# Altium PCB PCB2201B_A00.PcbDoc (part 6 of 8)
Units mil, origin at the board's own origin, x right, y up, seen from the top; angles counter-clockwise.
Board outline 4523.63 x 2358.23 mil, 6 copper layers (Top Layer, Signal Layer 2, Signal Layer 3, Signal Layer 4, Signal Layer 5, Bottom Layer), stack 61.221 mil thick; 383 components, 308 nets, 1386 pads, 1147 vias.
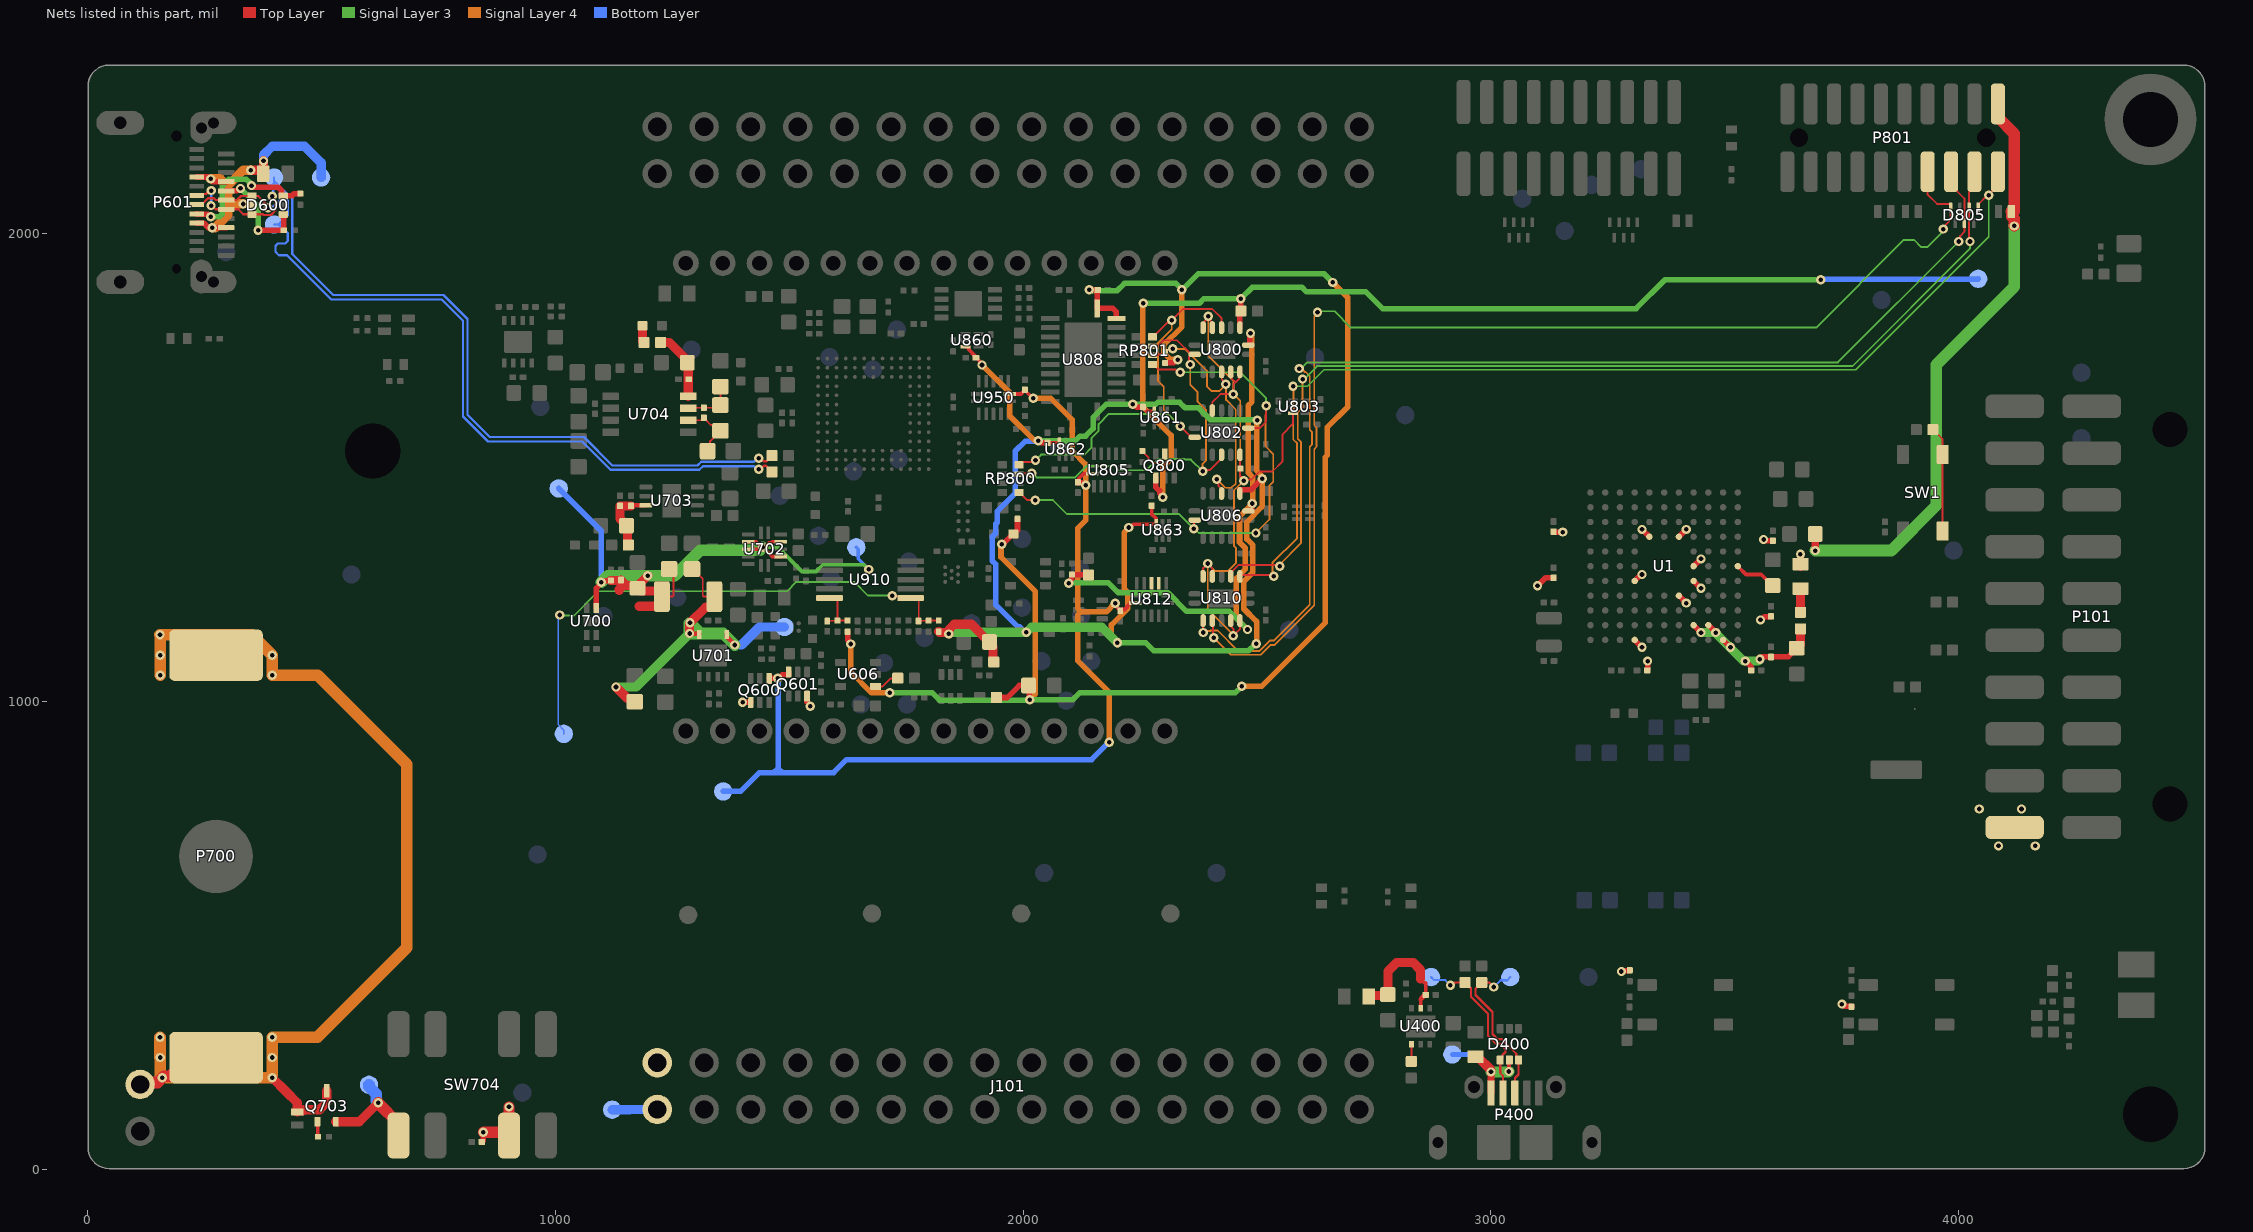
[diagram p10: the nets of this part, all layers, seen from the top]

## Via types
v1: diameter 19.68, hole 9.84, Top Layer to Bottom Layer, tented both sides, 768 vias
v2: diameter 20, hole 9.84, Top Layer to Bottom Layer, tented both sides, 379 vias

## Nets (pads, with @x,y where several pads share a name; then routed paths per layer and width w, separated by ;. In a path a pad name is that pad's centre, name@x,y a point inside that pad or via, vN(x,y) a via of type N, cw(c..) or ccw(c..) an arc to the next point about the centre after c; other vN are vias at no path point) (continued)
N17262717: C770.1 R769.1 R771.2 U704.6 | length 137.3
  Top Layer w3.94: U704.6@1284.67,1601.38 1312.99,1601.38 C770.1@1317.91,1606.3 1317.91,1605.51 1322.24,1601.18 1323.03,1601.18 1333.17,1591.04 1341.05,1591.04 R769.1@1353.35,1578.74 1331.35,1556.75 1331.35,1541 R771.2@1325.79,1535.43
N17262723: C770.2 R768.1 R769.2 U704.7 | length 110.9
  Top Layer w3.94: U704.7@1284.67,1626.97 1285.65,1627.95 C770.2@1317.91,1627.95 1347.44,1627.95 R769.2@1353.35,1633.86 R768.1@1353.35,1673.23
N17263058: C730.1 C731.1 R731.1 U704.8 | length 153.7
  Top Layer w19.68: R731.1@1225.39,1767.72 1244.09,1767.72 1282.48,1729.33 C731.1@1282.48,1724.41 1284.65,1722.24 1284.65,1654.74 1282.48,1654.74 U704.8@1284.67,1652.56
N17263074: L704.2 R731.2 | length 36.7
  Top Layer w19.68: L704.2@1187.01,1803.15 1187.01,1770.67 R731.2@1189.96,1767.72
N17356200: Q800.2 R815.1 | length 73.6
  Top Layer w3.94: R815.1@2254.95,1535.69 2254.95,1535.29 2267.93,1522.32 2267.93,1518.49 2276.57,1509.84 2290.35,1509.84 2303.15,1522.64 Q800.2@2303.15,1529.53
N17454530: D703.1 P700.1 Q703.3 ST701.2 | length 2370.9
  Top Layer w20: v2(395.51,196.11) 424.93,166.69 448.94,142.71 D703.1@448.94,122.95 451.06,125.08 460.66,125.08 463.48,127.9 496.76,127.9 511.81,142.95 Q703.3@511.81,168.31
  Top Layer w25: ST701.2@113.19,181.89 117.32,186.02 150.8,186.02 v2(160.89,196.11) 164.03,199.26 177.99,199.26 218.02,239.29 314.96,239.29 P700.1@327.87,226.38 ; P700.1@308.89,1099.29 P700.1@317.59,1107.99
  Signal Layer 4 w25: v2(155.81,282.73) 155.81,239.58 v2(155.97,239.42) 155.97,201.04 v2(160.89,196.11) v2(395.51,196.11) v2(395.51,239.42) v2(395.51,282.73) 492.14,282.73 683.15,473.74 683.15,865.98 493.02,1056.11 v2(395.51,1056.11) v2(395.51,1099.42) 352.2,1142.73 v2(155.81,1142.73) 155.97,1142.57 v2(155.97,1099.42) v2(155.97,1056.11)
N17454556: Q703.2 SW704.1 TP156.1 | length 236.1
  Top Layer w20: Q703.2@531.5,102.36 581.69,102.36 v1(622.05,142.72)
  Top Layer w25: v1(622.05,142.72) 622.05,141.73 665.35,98.43 665.35,91.54 SW704.1@665.35,72.83
  Bottom Layer w25: TP156.1@602.36,181.1 602.36,177.21 618.11,161.47 v1@618.11,146.65
N17454707: Q703.1 R792.2 | length 32.8
  Top Layer w8: Q703.1@492.13,102.36 492.8,101.69 492.8,70.83 R792.2@493.46,70.16
N17455720: L1.2 R2.1 | length 47.7
  Top Layer w19.68: L1.2@3660.43,1238.19 3661.42,1237.2 R2.1@3661.42,1190.94
N17455730: C3.1 C4.1 C5.1 R2.2 U1.K8 U1.K9 U1.L10 | length 381
  Top Layer w11.81: U1.K8@3433.07,1163.39 v1(3448.85,1147.59) ; U1.K9@3464.57,1163.39 v1(3480.35,1147.59) ; U1.L10@3496.06,1131.89 v1(3511.85,1116.09) ; v1(3543.3,1086.61) 3544.07,1086.61 3554.92,1075.76 3554.92,1067.32 3555.31,1066.93 C4.1@3556.1,1066.93 ; v1(3574.8,1090.55) 3579.72,1095.47 C5.1@3598.43,1095.47 3601.38,1095.47 3634.84,1095.47 ; 3635.83,1096.46 3634.84,1095.47 ; C3.1@3653.54,1114.17 3634.84,1095.47
  Top Layer w19.68: C3.1@3653.54,1114.17 3661.41,1122.04 R2.2@3661.42,1155.51
  Signal Layer 3 w19.68: v1(3448.85,1147.59) v1(3480.35,1147.59) 3480.35,1146.29 3540.03,1086.61 v1(3543.3,1086.61) 3570.86,1086.61 v1(3574.8,1090.55)
N17455955: C16.1 U1.F11 | length 92.7
  Top Layer w8: U1.F11@3527.56,1289.37 3545.28,1271.65 3577.76,1271.65 3601.2,1248.21 C16.1@3603.17,1248.21
N17456044: R7.2 SW1.3 SW1.4 | length 225.1
  Top Layer w3.94: R7.2@3944.36,1581.16 3965.23,1560.29 SW1.4@3965.23,1528.1 SW1.3@3965.23,1364.71
N17457251: D400.6 P400.3 R405.1 TPJ403.1 | length 361.8
  Top Layer w4.72: v1(3005.94,390.19) 2996.52,399.61 R405.1@2980.31,399.61 2966.95,386.24 2966.95,373.02 3003.19,336.78 3003.19,289.88 3014.58,278.5 3023.16,278.5 3054.04,247.62 3054.04,239.27 D400.6@3059.05,234.25 3059.05,203.15 3051.5,195.59 3051.5,163.96 P400.3@3051.2,163.66
  Bottom Layer w4.72: v1@3005.91,389.76 3020.8,404.66 3034.61,404.66 TPJ403.1@3041.35,411.39
N17457255: D400.4 P400.2 R406.1 TPJ404.1 | length 366.5
  Top Layer w4.72: v1(2913.39,393.7) 2917.43,393.7 2923.34,399.61 R406.1@2944.88,399.61 2957.5,386.99 2957.5,369.11 2993.74,332.87 2993.74,285.97 3010.66,269.05 3019.24,269.05 3031.1,257.19 3031.1,251.27 3024.7,244.87 3024.7,239.27 D400.4@3019.68,234.25 3019.68,206.14 3025.61,200.21 P400.2@3025.61,163.66
  Bottom Layer w4.72: TPJ404.1@2872.05,411.39 2878.55,404.9 2902.19,404.9 v1(2913.39,393.7)
N17457259: D400.5 L401.1 P400.1 TPJ405.1 | length 346.5
  Top Layer w7.87: v1(3038.39,209.65) 3038.39,233.27 D400.5@3039.37,234.25
  Top Layer w11.81: L401.1@2967.17,241.34 2968.9,241.34 2976.18,234.06 2976.18,232.48 v1(3000,208.66) 3000,189.36 2999.8,189.17 P400.1@2999.8,163.39
  Top Layer w15.75: P400.1@3000.02,163.66 v1(3000,208.66)
  Top Layer w19.68: L401.1@2968.9,241.34 2971.3,241.34 3000,212.64 v1(3000,208.66)
  Signal Layer 3 w23.62: v1(3000,208.66) 3037.4,208.66 v1(3038.39,209.65)
  Bottom Layer w9.84: TPJ405.1@2917.35,245.99 2962.67,245.99 v1(3000,208.66)
N17457715: C419.1 C423.1 L402.2 U400.2 | length 282.6
  Top Layer w7.87: 2849.53,407.48 2857.68,399.33 2860.16,399.33 2860.58,398.9 C419.1@2860.58,373.41 ; U400.2@2849.88,344.53 2849.88,363.49 2849.88,366.43 2854.49,371.05 C419.1@2857.43,371.05
  Top Layer w10: 2849.88,363.49 2857.43,371.05 2859.8,373.41 C419.1@2860.58,373.41
  Top Layer w19.68: L402.2@2738.78,370.08 2740.79,372.09 C423.1@2781.54,372.09 ; C423.1@2779.72,374.09 2779.72,423.43 2798.71,442.41 2833.78,442.41 2849.53,426.66 2849.53,407.48
N17457806: R408.2 U400.4 | length 36.9
  Top Layer w4: R408.2@2829.68,231.02 2829.68,239.12 2830.2,239.63 U400.4@2830.2,267.76
N17631739: R679.1 U606.1 | length 54.2
  Top Layer w3.94: U606.1@1685.04,1032.48 1699.8,1032.48 1716.54,1049.21 R679.1@1732.28,1049.21
SI_HEADER_ENABLE: R807.1 U800.5 U800.6 U800.12 U800.13 U802.5 U802.13 U803.3 U810.5 U810.6 U810.12 U810.13 | length 1429.8
  Top Layer w3.94: U810.6@2384.84,1267.72 2384.84,1285.43 v2(2394.68,1295.28) 2404.53,1285.43 U810.5@2404.53,1267.72 ; U800.6@2384.84,1799.21 2384.84,1809.22 2395.67,1820.04 v2(2395.67,1823.82) 2398.74,1820.75 2398.74,1815 2404.53,1809.22 U800.5@2404.53,1799.21 ; U802.5@2404.53,1622.05 2404.53,1639.76 2421.97,1657.2 v2@2444.18,1657.2 ; U810.12@2443.9,1173.23 2445.4,1171.72 2445.4,1159.91 2449.59,1155.72 v2(2449.59,1140.8) ; U800.12@2443.9,1704.72 2445.4,1703.22 2445.4,1691.43 2454.24,1682.59 ; v2(2449.52,1657.2) 2449.52,1677.87 2454.24,1682.59 ; v2@2450.79,1141.73 2463.58,1154.53 U810.13@2463.58,1173.23 ; U802.13@2463.58,1527.56 2463.58,1484.16 2471.46,1476.29 v2(2471.46,1471.94) 2474.03,1474.51 2487.36,1474.51 2504.7,1491.85 2533.19,1491.85 2554.65,1513.31 2554.65,1571.38 2576.77,1593.5 U803.3@2576.77,1616.14 ; U800.13@2463.58,1704.72 2462.08,1703.22 2462.08,1690.42 2454.24,1682.59
  Signal Layer 4 w3.94: v2(2395.67,1823.82) 2395.67,1739.17 2449.52,1685.32 v2(2449.52,1657.2) 2464.18,1642.55 2464.18,1477.76 2469.99,1471.94 v2(2471.46,1471.94) ; v2(2449.59,1140.8) 2450.66,1141.86 2394.68,1197.84 v2(2394.68,1295.28) 2411.14,1278.82 2437.29,1278.82 2455.42,1296.95 2455.42,1328.08 2450.79,1332.71 2450.79,1451.24 v2@2470.94,1471.39
SI_VCOM_CTS: D805.4 P801.8 U810.10 | length 2561.1
  Top Layer w3.94: U810.10@2404.53,1173.23 2406,1171.75 2406,1138.29 v2(2407.48,1136.81) ; P801.8@3930.12,2125.98 3933.07,2123.03 3933.07,2083.66 3953.31,2063.43 3980.51,2063.43 3982.28,2061.65 D805.4@3982.28,2055.71 3982.28,2029.53 3966.54,2013.78 v1(3966.54,2009.84)
  Signal Layer 3 w3.94: v1(2629.29,1832.33) 2628.94,1832.68 2630.57,1834.31 2665.69,1834.31 2700.79,1799.21 3694.88,1799.21 3882.33,1986.66 3903.98,1986.66 3919.29,1971.35 3932.52,1971.35 3963.52,2002.35 3963.52,2006.83 v1(3966.54,2009.84)
  Signal Layer 4 w3.94: v2(2407.48,1136.81) 2444.22,1100.07 2508.31,1100.07 2529.61,1121.37 2538.02,1121.37 2622.28,1205.63 2622.28,1539.63 2627.21,1544.56 2627.21,1586.28 2622.28,1591.21 2622.28,1822.14 2629.29,1829.15 v1(2629.29,1832.33)
SI_VCOM_RTS: D805.6 P801.6 U810.9 | length 2505.6
  Top Layer w3.94: U810.9@2384.84,1173.23 2384.92,1173.15 2384.92,1147.86 v2(2384.99,1147.79) ; P801.6@3983.27,2117.13 3983.27,2103.72 4011.81,2075.18 D805.6@4011.81,2023.03 ; v1(3999.84,1983.27) 4002.6,1986.02 4002.6,1994.91 4011.81,2004.12 D805.6@4011.81,2019.69
  Signal Layer 3 w3.94: v1(2590.16,1711.68) 2594,1711.68 2607.17,1724.85 3741.42,1724.85 v1(3999.84,1983.27)
  Signal Layer 4 w3.94: v2(2384.99,1147.79) 2388.06,1150.86 2399.65,1150.86 2401.07,1152.28 2415.63,1152.28 2459.97,1107.94 2505.04,1107.94 2527.55,1130.45 2535.96,1130.45 2612.67,1207.16 2612.67,1544.79 2617.61,1549.73 2617.61,1575.61 2612.67,1580.55 2612.67,1695.52 2603.7,1704.49 2601.61,1704.49 2594.42,1711.68 v1(2590.16,1711.68)
SI_VCOM_RXD: D805.1 P801.2 U810.2 | length 2306.1
  Top Layer w3.94: U810.2@2463.58,1267.72 2466.54,1270.67 2533.71,1270.67 v2(2536.09,1268.29) ; D805.1@4041.34,2055.71 4041.34,2062.4 4060.98,2082.05 v2(4063.82,2082.05) 4063.82,2083.16 4085.63,2104.97 P801.2@4085.63,2129.92
  Signal Layer 3 w3.94: v1(2577.19,1673.87) 2607.93,1673.87 2643.15,1709.1 3779.47,1709.1 4063.82,1993.45 v2(4063.82,2082.05)
  Signal Layer 4 w3.94: v2(2536.09,1268.29) 2533.02,1271.36 2533.02,1296.51 2585.59,1349.08 2585.59,1551.92 2577.38,1560.13 2577.38,1622.68 2577.76,1623.05 v1@2577.76,1671.26
SI_VCOM_TXD: D805.2 P801.4 U810.3 | length 2256.9
  Top Layer w3.94: U810.3@2443.9,1267.72 2443.9,1275.59 2460.64,1292.33 2545.41,1292.33 v2(2548.49,1289.26) ; D805.2@4021.65,2055.71 4021.65,2089.12 4032.48,2099.94 P801.4@4032.48,2134.84 ; D805.2@4021.85,2052.36 4021.85,1985.04 v2(4023.62,1983.27)
  Signal Layer 3 w3.94: v1(2597.36,1689.18) 2600.6,1689.18 2628.39,1716.97 3772.54,1716.97 4023.62,1968.05 v2(4023.62,1983.27)
  Signal Layer 4 w3.94: v2(2548.49,1289.26) 2548.49,1293.09 2593.73,1338.34 2593.73,1554.93 2586.99,1561.68 2586.99,1618.7 2597.44,1629.15 2597.44,1689.1 v1(2597.36,1689.18)
TCK_SWCLK: RP800.3 RP801.3 U800.8 U802.11 | length 873.6
  Top Layer w3.94: RP800.3@1991.14,1486.22 1992.13,1487.2 2017.72,1487.2 v2(2018.7,1488.19) ; RP801.3@2280.51,1759.84 RP801.3@2276.57,1759.84 2277.76,1761.02 2288.98,1761.02 2300.32,1772.36 2329.02,1772.36 2359.25,1742.13 U800.8@2359.72,1742.13 ; v2(2357.41,1720.56) 2354.74,1723.23 2354.74,1737.14 U800.8@2359.72,1742.13 ; U800.8@2367.13,1742.13 U800.8@2359.72,1742.13 ; v2(2383.86,1492.13) 2386.93,1495.2 2399.73,1495.2 2424.21,1519.68 U802.11@2424.21,1527.56
  Signal Layer 3 w3.94: v2(2018.7,1488.19) 2020.18,1488.19 2029.04,1479.33 2111.44,1479.33 2135.77,1503.66 2195.02,1503.66 2204.3,1494.37 2263.55,1494.37 2287.46,1518.28 2345.65,1518.28 2346.63,1517.29 2358.69,1517.29 v2(2383.86,1492.13)
  Signal Layer 4 w3.94: v2(2357.41,1720.56) 2357.41,1677.45 2372.69,1662.17 2372.69,1641.85 2390.75,1623.79 2390.75,1515.13 2383.86,1508.24 v2(2383.86,1492.13)
TDI: RP800.1 RP801.1 U802.1 U806.8 | length 1220.2
  Top Layer w3.94: RP800.1@1991.14,1446.85 1993.11,1446.85 2009.26,1430.7 v2(2026.5,1430.7) ; RP801.1@2276.57,1720.47 2278.54,1720.47 2289.02,1710 2325.29,1710 2331.55,1703.74 v2(2335.63,1703.74) ; v2@2367.13,1373.03 2365.16,1375 2365.16,1385.83 U806.8@2367.13,1387.8 ; U802.1@2481.3,1584.65 2505.68,1584.65 2519.31,1598.28 2519.31,1631.73 v2(2519.53,1631.95)
  Signal Layer 3 w3.94: v2(2026.5,1430.7) 2064.07,1430.7 2094.04,1400.73 2333.52,1400.73 v2(2365.16,1369.09) 2366.79,1369.09 2375.49,1360.39 v2(2497.75,1360.39) ; v2(2335.63,1703.74) 2464.57,1703.74 2519.53,1648.77 v2(2519.53,1631.95)
  Signal Layer 4 w3.94: v2(2497.75,1360.39) 2526.57,1389.21 2526.57,1461.58 2534.87,1469.88 2534.87,1528.88 2518.15,1545.6 2518.15,1612.66 2519.53,1614.04 v2(2519.53,1631.95)
TDO_SWO: R801.1 RP801.2 U800.11 U806.4 | length 561.4
  Top Layer w3.94: RP801.2@2276.57,1740.16 2290.35,1740.16 2292.81,1742.62 2299.36,1742.62 2303.69,1746.95 R801.1@2303.69,1747.34 2307.21,1750.86 2316.81,1750.86 v2(2319.88,1753.94) ; v2(2414.37,1475.39) 2417.44,1472.32 2417.44,1461.66 2424.21,1454.89 U806.4@2424.21,1444.88 ; U800.11@2424.21,1704.72 2424.72,1704.21 2424.72,1688.53 2433.38,1679.87 v2(2433.38,1678.19)
  Signal Layer 4 w3.94: v2(2319.88,1753.94) 2345.9,1753.94 2393.42,1706.42 2393.42,1673.29 2403.04,1663.67 2419.57,1663.67 2433.74,1677.84 v2(2433.38,1678.19) ; v2(2414.37,1475.39) 2414.37,1475.17 2432.57,1456.97 2445.38,1456.97 2454.44,1466.03 2454.44,1624.3 2434.05,1644.69 v2@2434.05,1676.18
TMS_SWDIO: RP800.4 RP801.4 U800.4 U802.8 | length 911.5
  Top Layer w3.94: RP800.4@1991.14,1505.91 1997.05,1511.81 v2@2018.7,1511.81 ; RP801.4@2276.57,1779.53 2278.54,1779.53 2313.98,1814.96 v2(2317.91,1814.96) 2342.24,1839.29 2403.82,1839.29 2424.21,1818.9 U800.4@2424.21,1799.21 ; v2(2335.63,1588.58) 2359.25,1564.96 U802.8@2367.13,1564.96
  Signal Layer 3 w3.94: v2@2029.53,1514.35 2029.53,1518.7 2038.66,1527.84 2131.41,1527.84 2146.23,1542.66 2146.23,1563.25 2161.42,1578.43 2161.42,1593.07 2183.13,1614.78 2309.43,1614.78 v2(2335.63,1588.58)
  Signal Layer 4 w3.94: v2(2317.91,1814.96) 2317.91,1796.12 2288.66,1766.87 2288.66,1685.09 2300.9,1672.86 2300.9,1623.31 v2(2335.63,1588.58)
  other v2: 2026.57,1515.75
USB_DM: D600.6 P601.A7 P601.B7 R902.1 TPJ612.1 | length 1811.8
  Top Layer w4.17: v1(264.84,2059.95) v1@267.16,2059.95
  Top Layer w4.72: P601.B7@234.25,2081.69 237.2,2084.65 253.99,2084.65 261.35,2092 v1(265.39,2092) ; v1@267.16,2059.95 274.95,2052.17 P601.A7@297.24,2052.17 322.76,2052.17 333.59,2041.34 D600.6@352.36,2041.34 375.68,2041.34 377.25,2039.77 393.08,2039.77 402.28,2048.97 402.28,2069.8 395.67,2076.41 v1(395.67,2079.84) ; v1(1435.04,1520.18) 1438.76,1520.18 1445.29,1513.65 1451.65,1513.65 R902.1@1463.58,1525.59
  Bottom Layer w4.17: v1(264.84,2059.95) v1@265.12,2060.23 ; v1@265.12,2091.73 v1(265.39,2092)
  Bottom Layer w4.72: v1@265.12,2060.23 v1@265.12,2091.73 ; v1(395.67,2079.84) 397.61,2081.78 397.61,2106.05 399.55,2107.99 TPJ612.1@399.55,2113.26 ; TPJ612.1@399.55,2120.11 TPJ612.1@399.55,2113.26 ; v1(1435.04,1520.18) 1432.35,1520.18 1424.79,1512.62 1312.07,1512.62 1304.21,1504.76 1122.5,1504.76 1061.95,1565.31 860.69,1565.31 812.72,1613.28 812.72,1817.86 761.6,1868.98 525.84,1868.98 438.23,1956.59 438.23,2074.58 TPJ612.1@399.55,2113.26
USB_DP: D600.4 P601.A6 P601.B6 R904.1 TPJ611.1 | length 1773.8
  Top Layer w4.72: P601.B6@234.25,2062.01 244.69,2062.01 258.34,2075.66 271.35,2075.66 275.16,2071.85 P601.A6@297.24,2071.85 319.95,2071.85 328.81,2080.71 D600.4@352.36,2080.71 352.79,2080.28 365.67,2080.28 386.57,2059.37 v1(386.57,2055.47) ; v1(1435.04,1496.56) 1439.09,1496.56 1446.67,1504.14 1450.59,1504.14 R904.1@1463.58,1491.14
  Bottom Layer w4.72: v1(386.57,2055.47) 389.36,2058.26 398.28,2058.26 416.31,2076.28 423.17,2076.28 428.78,2070.67 428.78,2039.57 TPJ611.1@408.92,2019.71 ; TPJ611.1@399.55,2019.71 TPJ611.1@408.92,2019.71 ; v1(1435.04,1496.56) 1431.41,1496.56 1424.79,1503.17 1315.98,1503.17 1308.13,1495.32 1118.58,1495.32 1058.03,1555.87 856.77,1555.87 803.27,1609.37 803.27,1813.95 757.69,1859.53 521.93,1859.53 427.32,1954.13 409.78,1954.13 402.55,1961.37 402.55,1973.86 407.98,1979.29 423.78,1979.29 428.78,1984.29 428.78,2001.64 419.34,2011.09 417.55,2011.09 TPJ611.1@408.92,2019.71
USBC_CC1: D600.1 P601.A5 R621.2 | length 210.1
  Top Layer w12: P601.A5@297.24,2091.54 v1@320.32,2091.54 ; v1(365.32,2007.35) R621.2@419.7,2007.35 ; R621.2@420.09,2012.99 D600.1@420.09,2040.54
  Signal Layer 3 w12: v1(327.71,2096.84) 365.32,2059.23 v1(365.32,2007.35)
USBC_CC2: D600.3 P601.B5 R620.2 | length 316.2
  Top Layer w12: P601.B5@234.25,2042.32 234.94,2041.64 258.01,2041.64 263.31,2036.34 v1(264.33,2036.34) ; v1(351.27,2102.83) 353.35,2102.83 357,2099.18 408.42,2099.18 415.45,2092.15 415.45,2082.09 416.83,2080.71 437.99,2080.71 442.55,2085.26 455.41,2085.26 R620.2@455.71,2085.63 R620.2@455.71,2085.63
  Signal Layer 3 w12: v1(264.33,2036.34) 282.76,2036.34 289.13,2042.72 289.13,2102.6 302.72,2116.18 340.4,2116.18 347.43,2109.15 347.43,2108.75 351.27,2104.91 v1(351.27,2102.83)
USBC_VBUS: D600.5 L600.1 P601.A4 P601.A9 P601.B4 P601.B9 TPJ613.1 | length 658.3
  Top Layer w12: P601.B4@234.25,2022.64 249.33,2022.64 259.17,2012.8 v1(267.17,2012.8) P601.A9@297.24,2012.8 ; P601.B9@234.25,2121.06 258.86,2121.06 262.8,2117.13 v1(263.98,2117.13) 263.98,2115.94 268.7,2111.22 P601.A4@297.24,2111.22 ; v1(333.72,2063.41) 334.92,2062.22 351.17,2062.22 D600.5@352.36,2061.02
  Top Layer w20: v1(349.53,2135.51) 349.76,2135.28 373.19,2135.28 373.19,2131.14 L600.1@376.38,2127.95 376.97,2128.54 v1(376.97,2155.51)
  Signal Layer 4 w20: v1(263.98,2117.13) 284.72,2117.13 294.72,2107.13 300.47,2101.38 ; v1(267.17,2012.8) 267.37,2013 274,2013 300.47,2039.47 300.47,2075.64 ; v1(333.72,2063.41) 333.21,2063.92 312.19,2063.92 300.47,2075.64 ; v1(349.53,2135.51) 333.37,2135.51 300.47,2102.62 300.47,2101.38 ; 300.47,2075.64 300.47,2101.38
  Bottom Layer w12: v1(267.17,2012.8) 267.87,2013.5 v1@267.87,2015.08
  Bottom Layer w20: v1(376.97,2155.51) 376.97,2168.12 395.85,2187.01 464.57,2187.01 499.95,2151.63 TPJ613.1@499.95,2120.11
V_SW: C800.1 C828.1 C950.1 Q600.4 Q601.6 TPJ608.1 U805.14 U812.14 U950.14 | length 2239.8
  Top Layer w7.87: U950.14@1971.85,1657.48 1995.87,1657.48 C950.1@2003.94,1665.55 ; C950.1@2003.94,1666.34 C950.1@2003.94,1665.55 ; v2(2021.65,1648.2) 2021.29,1648.2 C950.1@2003.94,1665.55 ; C800.1@2117.13,1468.5 2119.49,1470.87 2119.49,1477.41 2129.09,1487.01 U805.14@2148.23,1487.01 ; v2@2199.17,1203.19 C828.1@2207.68,1194.69 ; C828.1@2207.68,1193.9 C828.1@2207.68,1194.69 ; U812.14@2239.76,1210.63 2230.31,1210.63 2216.73,1197.05 2210.04,1197.05 C828.1@2207.68,1194.69
  Top Layer w11.81: Q600.4@1457.2,1049.61 1457.2,1049.74 1476,1049.74 v2(1476.14,1049.88) 1478.36,1049.88 1485.56,1057.09 1499.02,1057.09 Q601.6@1499.02,1062.99 ; C800.1@2117.13,1468.5 2117.13,1467.72 2117.52,1467.32 v2@2126.76,1467.32
  Signal Layer 4 w11.81: v2(2021.65,1648.2) 2059.64,1648.2 2105.59,1602.24 2105.59,1535.27 2133.7,1507.16 v2(2133.7,1462.6) 2133.7,1387.13 2116.85,1370.27 2116.85,1199.41 2124.33,1191.93 ; v2(2184.06,913.39) 2184.06,1020.45 2116.85,1087.66 2116.85,1185.24 2123.54,1191.93 2124.33,1191.93 ; v2(2196.85,1210.63) 2178.15,1191.93 2124.33,1191.93
  Bottom Layer w11.81: TPJ608.1@1359.25,808.11 1396.69,808.11 1436.75,848.17 1467.28,848.17 ; v2(1476.14,1049.88) v2@1478.36,1049.88 ; v2@1476.81,1049.21 1476.81,888.23 1476.5,887.91 1476.5,857.38 ; v2(2184.06,913.39) 2146.65,875.98 1623.19,875.98 1595.37,848.17 1485.71,848.17 ; 1467.28,848.17 1476.5,848.17 ; 1467.28,848.17 1476.5,857.38 ; 1476.5,848.17 1485.71,848.17 ; 1476.5,848.17 1476.5,857.38 ; 1476.5,857.38 1485.71,848.17
VCOM_CTS: U812.9
VCOM_RTS: U812.10
VCS: C710.1 C714.1 C728.1 R717.2 U703.7 | length 146.5
  Top Layer w9.84: C710.1@1163.39,1419.29 U703.7@1193.9,1419.29
  Top Layer w11.81: C710.1@1162.4,1418.31 C710.1@1163.39,1419.29
  Top Layer w19.68: R717.2@1156.5,1334.65 1154.53,1336.61 1154.53,1374.02 C714.1@1152.56,1375.98 1152.56,1376.97 1138.78,1390.75 C728.1@1138.78,1418.31 C710.1@1162.4,1418.31
VMCU: C6.1 C9.1 C10.1 C13.1 C14.1 C15.1 C706.1 D808.1 J101.1 J101.2 L1.1 P101.2 P801.1 Q600.1 Q601.3 R100.2 R101.2 SW704.3 TP703.1 U1.D5 U1.D7 U1.F8 U1.G4 U1.G8 U1.H7 U1.L4 | length 1882.2
  Top Layer w11.81: v2(1400.67,998.5) 1400.71,998.46 1417.83,998.46 Q600.1@1417.83,998.61 ; Q601.3@1538.39,1011.81 1538.39,999.26 1545.28,992.37 v2(1545.28,990.16) ; v1(3278.69,423.25) 3280.2,424.75 3295.42,424.75 3295.91,425.24 3296.3,425.24 3296.69,425.63 R101.2@3296.69,426.02 ; U1.L4@3307.09,1131.89 v1(3322.85,1116.09) ; U1.G4@3307.09,1257.87 3320.87,1271.65 v1(3322.83,1271.65) ; v1(3322.85,1368.09) U1.D5@3338.58,1352.36 ; U1.H7@3401.57,1226.38 v1(3417.35,1210.59) ; U1.D7@3401.62,1352.36 v1(3417.35,1368.09) ; U1.G8@3433.07,1257.87 v1(3448.85,1242.09) ; U1.F8@3433.07,1289.37 3433.12,1289.37 v1(3448.85,1305.09) ; v1(3582.67,1346.45) 3585.62,1343.5 C15.1@3602.36,1343.5 ; v1(3750,353.69) 3752.13,353.69 3757.2,348.62 3770.04,348.62 3770.43,348.23 R100.2@3770.43,347.83
  Top Layer w12: C706.1@843.5,59.06 846.46,62.01 v1@846.46,78.74 ; v1(3099.41,1247.59) 3116.58,1264.76 C13.1@3133.86,1264.76 ; C9.1@3133.86,1363.19 3134.84,1362.2 v1(3153.54,1362.2) ; v1@3280.2,424.75 3280.64,425.2 v1@3282.48,425.2 ; C14.1@3334.65,1069.88 v1(3334.65,1086.61) ; v1(3576.07,1174.75) 3578.15,1174.75 3584.7,1181.3 3598.13,1181.3 3598.43,1181.6 C6.1@3598.43,1182.09 ; v1(3750,353.69) v1@3753.05,350.65
  Top Layer w15.75: v1(3661.32,1314.86) 3661.42,1314.76 L1.1@3661.42,1287.4 ; v1(3692.91,1322.83) C10.1@3692.91,1354.33
  Top Layer w23.62: v1@847.16,79.72 890.75,79.72 901.57,68.9 SW704.3@901.57,72.83 v1(901.57,133.86)
  Top Layer w25: P801.1@4085.77,2246.22 4118.11,2213.88 D808.1@4118.11,2047.24 ; D808.1@4112.2,2047.24 4113.48,2045.96 4113.48,2036.37 4118.11,2031.74 v1(4118.11,2016.73)
  Signal Layer 3 w25: v1(3692.91,1322.83) 3855.24,1322.83 3951.5,1419.09 3951.5,1720.2 4118.11,1886.81 v1(4118.11,2016.73)
  Bottom Layer w19.68: TP703.1@1122.05,127.95 1122.09,127.91 1159.37,127.91 1159.88,128.43 J101.1@1218.5,128.43
  other v1: 846.46,79.72 4084.54,691.73 4163.28,691.73 4043.31,770.47 4133.86,770.47
VMCU_BUF: C625.1 C861.1 C863.1 C865.1 C867.1 R630.2 R675.2 U806.2 U860.6 U861.6 U862.6 U863.6 | length 3228.8
  Top Layer w7.87: U860.6@1876.93,1758.23 1883.82,1758.23 1883.82,1752.34 1896.26,1739.9 1896.26,1737.17 1898.62,1734.8 1900.2,1734.8 1912.4,1722.6 v2(1912.4,1719.49) ; C861.1@2052.17,1553.15 U862.6@2077.76,1553.15 ; v2(2225.95,1372.05) 2229.23,1372.05 2236.12,1378.94 2284.45,1378.94 2284.45,1391.18 2274.8,1400.83 C867.1@2274.8,1418.54 ; C865.1@2255.98,1629.04 2256.28,1629.04 2258.74,1626.57 2258.74,1626.28 2264.94,1620.08 U861.6@2280.51,1620.08
  Top Layer w11.81: v2@1911.22,1719.49 v2(1912.4,1719.49) ; v2@2038.39,1553.15 C861.1@2052.17,1553.15 ; v2(2234.25,1635.83) 2236.47,1635.83 2243.26,1629.04 C865.1@2255.98,1629.04 ; U806.2@2463.58,1444.88 2463.58,1452.53 2487.26,1452.53 v2(2511.11,1476.38)
  Top Layer w19.68: R630.2@1819.88,1149.61 1821.77,1147.72 v2@1835.54,1147.72 ; v2(1841.54,1144.69) 1841.6,1144.75 1841.6,1153.73 1853.22,1165.35 1889.76,1165.35 C625.1@1928.15,1126.97 ; C625.1@1928.15,1125.98 1928.15,1125 1935.81,1117.34 1935.81,1086.28 R675.2@1937.48,1084.61
  Signal Layer 3 w11.81: v2@2033.46,1556.1 2034.52,1557.16 2111.41,1557.16 2121.87,1567.62 2133.9,1567.62 2149.61,1583.32 2149.61,1607.28 2178.15,1635.83 v2(2234.25,1635.83) 2283.81,1635.83 2287.53,1639.54 2334.87,1639.54 2346.74,1627.67 2375.28,1627.67 2400.59,1602.36 2499.02,1602.36 2499.02,1601.17 v1(2500.55,1601.17) ; v2(2201.77,1125.98) 2261.93,1125.98 2279.64,1108.27 2481.28,1108.27 2496.42,1123.41 v2(2498.64,1123.41)
  Signal Layer 3 w19.68: v2(1841.54,1144.69) 1841.62,1144.69 1845.01,1148.07 v2(2007.13,1148.07) 2007.21,1148.07 2018.31,1159.17 2168.06,1159.17 2198.44,1128.78 2198.89,1128.78 2201.69,1125.98 v2(2201.77,1125.98)
  Signal Layer 4 w11.81: v2(1912.4,1719.49) 1971.68,1660.21 1971.68,1610.82 2023.77,1558.73 2031.02,1558.73 v2(2032.59,1557.16) ; v2(2201.77,1125.98) 2201.77,1128.2 2188.71,1141.27 2188.71,1163.91 2224.13,1199.33 2224.13,1233.66 2215.83,1241.96 2215.83,1361.03 2225.95,1371.16 v2(2225.95,1372.05) ; v2@2497.54,1124.51 v2(2498.64,1123.41) ; v2@2499.24,1126.97 2499.02,1127.19 2499.02,1171.26 2471.74,1198.54 2471.74,1257.05 2491.14,1276.46 2491.14,1334.28 2478.35,1347.07 2478.35,1384.25 2511.11,1417.01 v2(2511.11,1476.38) ; v1(2500.55,1601.17) 2499.87,1601.17 2499.02,1600.31 2499.02,1494.09 v2@2508.86,1484.25
  Bottom Layer w11.81: 1941.82,1364.53 1941.82,1360 ; v2(2007.13,1148.07) 2004.91,1148.07 1993.44,1159.55 1989.07,1159.55 1941.82,1206.81 1941.82,1293.22 1933.94,1301.1 1933.94,1352.13 1941.82,1360 ; v2(2032.59,1557.16) 2032.35,1556.92 2004.87,1556.92 1982.99,1535.04 1982.99,1445.08 1945.16,1407.26 1945.16,1383.27 1941.82,1379.92 1941.82,1360
VMCU_R: R701.1 R702.2 R709.2 TP700.1 U701.1 U701.4 | length 791.3
  Top Layer w3.94: R709.2@1292.6,1283.46 1294.62,1283.46 1315.61,1262.48 1315.61,1226.72 1317.91,1224.41 R701.1@1340.55,1224.41
  Top Layer w9.84: v2(1287.4,1145.67) 1288.39,1144.69 1308.07,1144.69 U701.4@1308.07,1143.7 ; U701.1@1367.13,1143.7 1367.13,1138.78 1383.86,1122.05 v2(1383.86,1121.06)
  Top Layer w19.68: v1(1130.19,1031.32) 1154.79,1006.72 1163.37,1006.72 R702.2@1170.26,999.83 ; v2(1287.4,1145.67) v2@1287.4,1168.31 ; v2(1288.39,1168.31) 1321.85,1201.77 1333.66,1201.77 1340.55,1208.66 R701.1@1340.55,1224.41
  Signal Layer 3 w19.68: v1(1130.19,1031.32) 1173.05,1031.32 v2(1287.4,1145.67)
  Signal Layer 3 w25: v2@1287.4,1167.32 v2(1287.4,1145.67) 1308.07,1145.67 ; v2(1288.39,1168.31) 1308.07,1148.62 1308.07,1145.67 ; v2(1383.86,1121.06) 1359.25,1145.67 1308.07,1145.67
  Bottom Layer w20: v2(1383.86,1121.06) 1398.39,1121.06 1436.78,1159.45 TP700.1@1490.16,1159.45
VMCU_S: C700.1 C701.1 R701.2 R710.2 R760.2 TP701.1 TP705.1 U700.3 U702.2 U702.4 U702.9 U702.10 | length 1501.1
  Top Layer w3.94: R701.2@1228.35,1224.41 1250.98,1224.41 1253.29,1226.72 1253.29,1273.87 R710.2@1243.7,1283.46
  Top Layer w7.87: U702.10@1412.99,1325.79 1436.7,1325.79 1440.7,1329.79 v2(1443.98,1329.79) v2@1444.86,1329.79 ; U702.9@1412.99,1341.54 1430.12,1341.54 v2@1438.98,1332.68 ; U702.2@1482.68,1310.04 1464.61,1310.04 v2@1444.86,1329.79 ; U702.4@1482.68,1341.54 1464.61,1341.54 1462.45,1339.37 1456.84,1339.37 1447.26,1329.79 v2@1444.86,1329.79
  Top Layer w11.81: v2(1098.42,1254.92) 1100.64,1254.92 1103.79,1258.07 1118.7,1258.07 1119.09,1258.46 R760.2@1119.09,1258.86
  Top Layer w12.01: U700.3@1087.6,1199.8 1087.6,1241.93 1098.43,1252.76 v2@1098.43,1252.95
  Top Layer w19.68: R760.2@1119.09,1258.86 C701.1@1140.75,1258.86 ; 1137.05,1238.03 1137.05,1239.5 1140.75,1243.2 C701.1@1140.75,1258.86 ; C701.1@1140.75,1259.84 C701.1@1140.75,1258.86 ; C700.1@1177.17,1242.13 1183.07,1248.03 1183.07,1253.85 v2(1198.06,1268.93) v2(1198.06,1268.93) ; 1179.92,1203.66 1223.5,1203.66 1228.35,1208.5 R701.2@1228.35,1224.41 1228.35,1229.33 1221.46,1236.22 1182.09,1236.22 1170.28,1248.03 1151.58,1248.03 C701.1@1140.75,1258.86
  Signal Layer 3 w7.87: v2(1443.98,1329.79) 1476.18,1329.79 1527.78,1278.19 1557.72,1278.19 1571.85,1292.32 1660.03,1292.32 1669.73,1282.63 v1(1670.55,1282.63)
  Signal Layer 3 w25: v2(1098.42,1254.92) 1112.43,1268.93 v2(1198.06,1268.93) 1255.46,1268.93 1310.31,1323.78 1437.97,1323.78 v2(1443.98,1329.79)
  Bottom Layer w7.87: TP705.1@1643.7,1329.72 1647.97,1325.45 1647.97,1305.2 v1(1670.55,1282.63)
  Bottom Layer w12.01: TP701.1@1007.87,1455.71 1098.42,1365.16 v2(1098.42,1254.92)
VMCU_SENSE: C632.1 R630.1 R631.2 TP708.1 U910.6 | length 1156.3
  Top Layer w3.94: v2(1720.58,1226.49) 1723.1,1223.97 1757.33,1223.97 U910.6@1759.84,1221.46 1773.34,1221.46 1777.28,1217.52 1777.28,1172.95 C632.1@1776.57,1172.24 1777.07,1172.74 1797.74,1172.74 R631.2@1798.23,1173.23 R630.1@1819.88,1173.23
  Signal Layer 3 w3.94: v1@1013.44,1184.06 1040.65,1184.06 1092.5,1235.91 1495.74,1235.91 1515.79,1255.95 1639.28,1255.95 1668.75,1226.49 v2(1720.58,1226.49)
  Bottom Layer w3.94: v1@1006.89,1183.73 1006.89,951.13 1018.7,939.31 TP708.1@1018.7,931.1
  other v1: 1009.84,1185.04
VTARGET: R629.2 R691.1 U800.1 U806.1 | length 1207.5
  Top Layer w11.81: v2(2097.44,1252.95) 2097.44,1255.17 2103.94,1261.66 2103.94,1271.26 2104,1271.32 2139.47,1271.32 R691.1@2139.8,1270.98 ; R629.2@2104.72,1272.39 R629.2@2104.72,1272.44 ; U806.1@2481.3,1407.48 2488.59,1407.48 2488.59,1421.94 v2(2490.16,1423.51) ; U800.1@2481.3,1761.81 2484.65,1761.81 2484.65,1785.83 v2(2486.22,1787.4)
  Signal Layer 3 w11.81: v2@2098.43,1253.94 2098.78,1254.29 2181.85,1254.29 2203.16,1232.98 2309.46,1232.98 2349.52,1192.91 2441,1192.91 v1(2479.77,1154.15)
  Signal Layer 4 w11.81: v1(2479.77,1154.15) 2455.99,1177.93 2455.99,1263.58 2475.39,1282.98 2475.39,1327.76 2462.6,1340.55 2462.6,1395.95 v2(2490.16,1423.51) ; v2(2486.22,1787.4) 2486.22,1785.19 2489.17,1782.24 2489.17,1640.37 2481.3,1632.5 2481.3,1489.54 2490.86,1479.98 v2@2490.86,1425.9
VTARGET_BUF: C655.1 C806.1 L801.1 R636.2 R687.2 R801.2 R809.2 U808.23 U808.24 | length 3393.7
  Top Layer w11.81: R636.2@1625,1149.61 1625,1149.21 1625.39,1148.82 1625.39,1132.04 1632.17,1125.27 v2(1632.17,1123.05) ; R687.2@1942.91,1008.86 1966.54,1008.86 1992.32,1034.65 2011.61,1034.65 C655.1@2011.81,1034.45 2012.94,1033.32 2012.94,1005.06 v2(2014.06,1003.94) ; v2(1954.37,1336.09) 1956.16,1336.09 1978.35,1358.27 1980.32,1358.27 1988.19,1366.14 R809.2@1988.19,1390.75 ; v2(2141.73,1879.92) C806.1@2159.45,1879.92 2158.46,1878.94 U808.24@2158.46,1840.35 2192.13,1840.35 2199.61,1832.87 U808.23@2199.61,1818.9 ; R801.2@2303.69,1723.72 2303.79,1723.82 2322,1723.82 2328.49,1730.32 v2(2330.71,1730.32)
  Signal Layer 3 w11.81: v2(1715.55,1018.7) 1806.1,1018.7 1821.55,1003.26 2013.38,1003.26 v2(2014.06,1003.94) ; v2@2015.07,1003.26 2015.75,1003.94 2106.02,1003.94 2120.78,1018.7 2453.46,1018.7 v2(2467.52,1032.76) ; v2(2141.73,1879.92) 2143.3,1878.35 2149.09,1878.35 2149.21,1878.23 2201.41,1878.23 2216.87,1893.7 2326.49,1893.7 2339.57,1880.63 v2(2339.57,1880.2) ; v2@2340.06,1879.71 2374.38,1914.03 2643.67,1914.03 v2(2661.86,1895.84)
  Signal Layer 4 w11.81: v2(1632.17,1123.05) 1632.17,1062.97 1676.44,1018.7 v2(1715.55,1018.7) ; v2(1954.37,1336.09) 1952.95,1334.67 1952.95,1308.92 2026.53,1235.33 2026.53,1016.41 v2(2014.06,1003.94) ; v2(2330.71,1730.32) 2329.14,1731.88 2314.49,1731.88 2300.48,1745.9 2300.48,1761.98 2339.57,1801.07 v2(2339.57,1880.2) ; v2(2467.52,1032.76) 2510.01,1032.76 2645.43,1168.18 2645.43,1521.81 2649.93,1526.3 2649.93,1585.95 2693.9,1629.92 2693.9,1863.8 v2(2661.86,1895.84)
VTARGET_SENSE: C638.1 R636.1 R637.2 U910.5 | length 106.4
  Top Layer w3.94: C638.1@1581.69,1172.24 1582.19,1172.74 1602.85,1172.74 R637.2@1603.35,1173.23 ; U910.5@1586.61,1221.46 1599.41,1221.46 1603.35,1217.52 R637.2@1603.35,1173.23 ; R636.1@1625,1173.23 R637.2@1603.35,1173.23
VTREF: Q800.4 R816.2 TPJ817.1 U800.2 | length 2420.1
  Top Layer w11.81: Q800.4@2283.46,1478.35 2283.46,1458.47 2291.73,1450.2 2291.73,1445.72 2298.23,1439.22 v2(2298.23,1437.01) ; U800.2@2463.58,1799.21 2463.58,1832.68 R816.2@2465.55,1834.65 v2(2465.58,1861.05)
  Signal Layer 3 w11.81: v2(2256.89,1851.38) 2376.85,1851.38 2386.53,1861.05 v2(2465.58,1861.05) 2490.07,1885.55 2596.11,1885.55 2606.18,1875.47 2732.8,1875.47 ; 2745.6,1862.67 2732.8,1875.47 ; v1(3704.72,1901.57) 3372.05,1901.57 3310.27,1839.79 2768.47,1839.79 2732.8,1875.47
  Signal Layer 4 w11.81: v2(2256.89,1851.38) 2255.36,1849.85 2255.36,1630.28 2316.65,1568.98 2316.65,1518.61 2298.23,1500.19 v2(2298.23,1437.01)
  Bottom Layer w11.81: v1(3704.72,1901.57) 3705.69,1902.54 4040.28,1902.54 TPJ817.1@4041.25,1903.51
pads on no net: D400.3 D800.5 D801.1 J101.21 J101.22 J101.23 J102.11 M2.1 M3.1 P101.M1 P101.M2 P601.25@70.87,2237.01 P601.26@70.87,1896.85 P601.27@244.09,2225.39 P601.27@269.68,2237.01 P601.28@244.09,1908.46 P601.28@269.69,1896.85 P601.A2 P601.A3 P601.A8 P601.A10 P601.A11 P601.B2 P601.B3 P601.B8 P601.B10 P601.B11 P601.M1 P601.M2 P800.7 P800.11 P800.13 P801.10 P801.12 P801.14 P801.16 P801.18 P801.20 P801.M1 P801.M2 RP800.2 RP800.7 SW704.5 U600.8 U701.8 U800.17 U802.17 U806.17 U808.8 U808.9 U808.10 U810.17 U900.B11 U900.E12 U900.F12 U900.G2 U900.H2 U900.J2 U900.L3 U900.L8 U900.L12 U900.M4 U900.M12 U900.M13 U900.N7 U900.N12 U901.9 U902.C1
copper on no net: | length 1
  Bottom Layer w11.81: 2152.56,1619.09 2153.26,1619.8

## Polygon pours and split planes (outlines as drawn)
GND on Bottom Layer "GND_L8" (solid, remove dead copper, pour order 30): 0,0 6.89,2368.11 4731.3,2368.11 4731.3,0 1208.66,0 1208.66,370.08 2389.76,370.08 2389.76,724.41 1208.66,724.41 1208.66,0
GND on Bottom Layer "GND2_L8" (hatched 90Degree grid 39.37 track 8, pour order 33): 1180.49,334.65 1180.49,763.78 2400.24,763.78 2400.24,334.65
3V3 on Signal Layer 5 "3V3_L5" (solid, remove dead copper, pour order 25): 4507.87,2342.52 19.68,2342.52 19.68,19.68 944.88,19.68 4499.44,19.68
5V on Signal Layer 5 "5V_L5" (solid, remove dead copper, pour order 24): 885.83,2042.54 949.25,2105.97 2598.09,2105.97 2696.84,2204.72 2755.91,2204.72 2853.07,2107.56 4015.75,2106.02 4015.75,2344.03 769.22,2344.03 629.92,2204.72 452.76,2204.72 452.76,2203.74 374.33,2203.74 334.78,2164.19 334.78,1972.14 714.33,1592.59 972.87,1334.06 1204.66,1334.05 1338.58,1200.14 1377.3,1200.14 1429.41,1257.41 1429.41,1365.91 1442.91,1379.42 1442.91,1540.55 1311.22,1672.24 979.57,1672.24 970.87,1680.94 970.87,1782.15 885.83,1867.19
VMCU on Signal Layer 5 "VMCU_L5" (solid, remove dead copper, pour order 23): 2723.03,1397.83 2809.84,1484.65 2821.18,1485.04 3482.21,1485.04 3569.94,1566.14 4175.06,1566.14 4212.6,1603.68 4212.6,1924.37 4192.44,1944.57 4192.44,1948.82 4147.8,1948.82 4138.94,1958.05 4138.94,2074.92 4150.63,2086.61 4509.42,2086.61 4509.42,17.99 2580.52,17.99 885.83,18.19 839.57,17.72 832.68,24.61 832.68,99.41 839.57,106.3 871.06,106.3 885.83,120.08 885.83,128.94 885.83,196.85 968.5,279.53 2411.42,279.53 2514.76,176.18 2750.98,176.18 2750.98,178.15 2783.46,210.63 2782.48,211.61 2782.48,340.55 2775.1,350.89 2756.89,369.09 2397.64,369.09 2389.76,376.97 2389.76,726.38 2388.78,727.36 1158.46,727.36 1141.73,743.11 1141.73,885.83 1274.25,1018.35 1566.85,1018.35 1652.6,1102.36 2170.23,1102.36 2465.71,1397.83
GND on Top Layer "GND_L1" (solid, remove dead copper, pour order 45): -5.91,4.92 -5.91,1313.98 -5.91,2367.13 4718.5,2367.13 4718.5,4.92
VMCU_S on Top Layer "VMCU_S_L01_P027" (solid, remove dead copper, pour order 27): 1082.83,1189.49 1105.87,1189.49 1109.76,1193.39 1109.76,1217.83 1117.2,1225.28 1138.29,1225.28 1169.66,1193.91 1241.21,1193.91 1241.21,1250.09 1238.61,1252.69 1213.28,1252.69 1213.28,1267.74 1204.13,1276.89 1192.81,1276.89 1192.81,1275.25 1175.84,1258.27 1154.7,1258.27 1144.52,1268.46 1090.74,1268.46 1082.13,1259.84 1082.13,1190.02 1082.3,1190.02
3V3 on Top Layer "3V3_L01_P036" (solid, remove dead copper, pour order 36): 946.75,1715.34 946.75,1732.23 954.06,1732.23 960.67,1738.84 1015.31,1738.84 1021.45,1732.69 1021.45,1690.47 1014.03,1683.04 985.78,1683.04 972.85,1695.97 954.67,1714.14 947.88,1714.14 947.88,1714.21
5V on Top Layer "5V_L01_P034" (solid, remove dead copper, pour order 34): 925.67,1675.2 925.81,1675.06 925.81,1630.29 906.33,1610.81 871.97,1610.81 855.74,1627.04 855.74,1669.79 859.77,1673.82 896.78,1673.82 899.65,1676.69 899.66,1676.67 924.31,1676.67 924.31,1676.63 925.49,1675.45 928.6,1678.57 928.6,1681.32
USBC_VBUS on Top Layer "USBC_VBUS_L01_P038" (solid, remove dead copper, pour order 38): 387.28,2116.96 387.28,2167.7 379.78,2175.21 346.83,2175.21 328.67,2157.04 328.67,2127.4 339.29,2116.77 387.28,2116.77
5V on Top Layer "5V_L01_P039" (solid, remove dead copper, pour order 39): 417.62,2113.36 416.99,2113.98 416.99,2166.32 423.78,2173.11 466.65,2173.11 475.51,2164.25 475.51,2120.67 465.29,2110.45 416.34,2110.45 410.51,2116.28
N17457715 on Top Layer "N17457715_L01_P040" (solid, remove dead copper, pour order 40): 2866.19,367.89 2854.32,356.01 2854.32,350.31 2846.03,350.31 2839.77,356.57 2839.77,365.77 2835.44,370.1 2835.44,432.33 2839.65,436.54 2845.46,436.54 2868.46,413.54 2868.46,378.4 2868.46,373.41
5V on Top Layer "5V_L01_P041" (solid, remove dead copper, pour order 41): 2735.14,473.1 2733.09,475.16 2662.09,475.16 2640.83,453.9 2640.83,366.38 2653.23,353.98 2653.33,354.07 2704.65,354.07 2704.65,407.88 2740.91,444.13 2740.91,469.25 2737.06,473.1
EFM_USB_VBUS on Top Layer "EFM_USB_VBUS_L01_P042" (solid, remove dead copper, pour order 42): 2845.49,272.83 2845.49,251.5 2874.91,222.08 2927.76,222.08 2933.39,227.71 2933.39,271.42 2847.25,271.42 2849.88,268.79 2849.88,267.76
GND on Signal Layer 4 "GND_L4" (solid, remove dead copper, pour order 37): 0,0 0,2362.21 4525.62,2362.2 4525.62,0
USBC_VBUS on Signal Layer 4 "USBC_VBUS_L04_P029" (solid, remove dead copper, pour order 29): 394.37,2175.24 392.95,2176.65 354.68,2176.65 332.72,2154.69 255.83,2154.69 239.17,2138.03 239.17,1997.36 251.57,1984.96 317.48,1984.96 345.12,2012.6 345.12,2069.29 336.26,2078.15 319.61,2078.15 311.1,2086.65 311.1,2107.91 320.79,2117.6 377.49,2117.6 394.25,2134.37 394.02,2134.6 394.02,2174.53
GND on Signal Layer 2 "GND_L2" (solid, remove dead copper, pour order 26): 0,0 0,2362.21 4724.41,2362.2 4724.41,0
GND on Signal Layer 3 "GND_L3" (solid, remove dead copper, pour order 28): 0,0 0,2362.21 4525.62,2362.2 4525.62,0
